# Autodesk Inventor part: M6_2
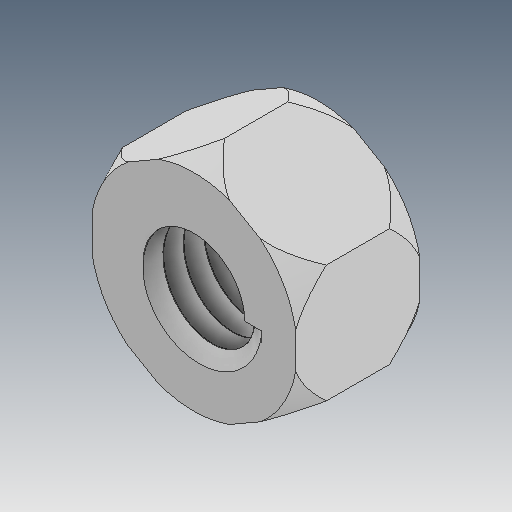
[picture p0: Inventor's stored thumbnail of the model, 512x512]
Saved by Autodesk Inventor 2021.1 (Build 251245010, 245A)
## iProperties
Created: 2019-04
Part Number: M6_2
Material: Ogólny
Document SubType Name: Modeling
Designer: user
Density: 1 g/cm^3
Appearance: Domyślna
Author: user
Revision Number: ÈÎºÎ
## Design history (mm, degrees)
feature "ÊäÈë1"
node "Bryła1"
